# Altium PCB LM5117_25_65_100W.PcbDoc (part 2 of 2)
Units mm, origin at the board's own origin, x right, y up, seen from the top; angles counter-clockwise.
Board outline 73.02 x 159.13 mm, 4 copper layers (Top Layer, GND, Power, Bottom Layer), stack 0.742 mm thick; 149 components, 80 nets, 535 pads, 514 vias.
Unrouted connection lines stored in the file: 2.
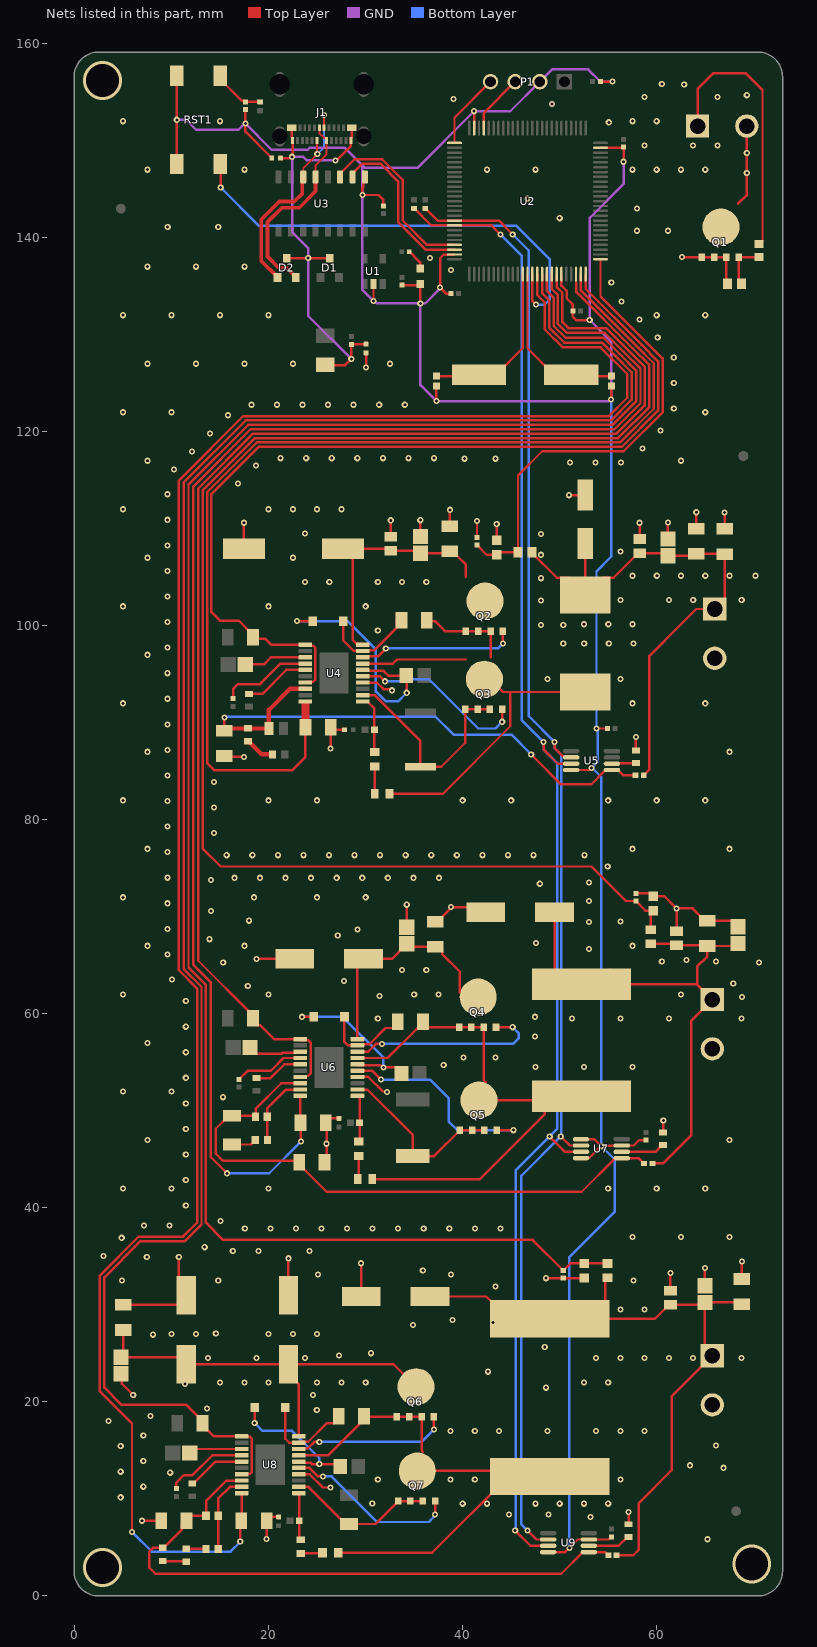
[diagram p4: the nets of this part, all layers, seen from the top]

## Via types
v1: diameter 0.635, hole 0.305, Top Layer to Bottom Layer, 475 vias
v2: diameter 0.5, hole 0.2, Top Layer to Bottom Layer, 36 vias
v3: diameter 4, hole 3.4, Top Layer to Bottom Layer, 3 vias

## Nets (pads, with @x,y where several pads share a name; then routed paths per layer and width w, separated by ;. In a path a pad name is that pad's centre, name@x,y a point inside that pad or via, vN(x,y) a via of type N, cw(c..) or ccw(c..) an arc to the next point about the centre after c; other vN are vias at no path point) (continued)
buck1_EN: C22.1 U2.25 U4.1 U4.7 | length 95.7
  Top Layer w0.254: U4.7@23.847,94.148 23.945,94.246 24.653,94.246 24.874,94.467 24.874,97.729 24.653,97.95 23.945,97.95 U4.1@23.847,98.048 20.316,98.048 19.685,98.679 18.572,98.679 C22.1@18.445,98.806 18.445,99.057 16.968,100.534 15.036,100.534 14.157,101.413 14.157,113.577 19.017,118.437 56.454,118.437 60.201,122.184 60.201,127.251 58.477,128.975 52.736,134.716 U2.25@52.736,136.239
buck1_FB: C14.1 C32.2 R7.1 R13.1 U4.8 U5.5 | length 58.7
  Top Layer w0.254: v1(15.494,90.551) C32.2@15.494,89.184 C32.2@15.718,89.408 ; v1(47.117,86.741) 50.203,83.655 53.302,83.655 54.778,85.131 56.065,85.131 56.614,84.582 R13.1@57.868,84.582
  Top Layer w0.45: C32.2@15.718,89.408 C14.1@20.078,89.408 20.078,91.325 22.251,93.498 U4.8@23.847,93.498
  Bottom Layer w0.254: v1(15.494,90.551) 15.548,90.605 37.284,90.605 39.116,88.773 45.085,88.773 v1(47.117,86.741)
buck1_Iout: C19.2 U2.24 U4.10 | length 111
  Top Layer w0.254: C19.2@23.846,89.535 23.846,86.457 22.479,85.09 14.478,85.09 13.703,85.865 13.703,113.765 18.829,118.891 56.266,118.891 59.747,122.372 59.747,127.063 58.023,128.787 52.236,134.574 U2.24@52.236,136.239
  Top Layer w0.8: C19.2@23.847,89.536 23.847,91.948
buck1_RAMP: C29.1 R12.1 U4.11 | length 6
  Top Layer w0.254: U4.11@29.747,92.198 30.222,92.198 30.959,91.461 C29.1@30.959,89.281 30.959,87.012 R12.1@30.988,86.983
buck1_VCC: C24.1 D4.1 U4.16 | length 25.8
  Top Layer w0.254: v1@22.987,100.457 D4.1@24.587,100.457 ; U4.16@29.747,95.448 29.845,95.35 31.904,95.35 32.385,94.869 C24.1@34.253,94.869 34.29,94.832 v1(34.29,93.091)
  Bottom Layer w0.254: v1(22.96,100.475) 28.176,100.475 31.115,97.536 31.115,93.218 32.131,92.202 33.401,92.202 v1(34.29,93.091)
buck1_Vout: C31.2 R15.1 R16.2 U2.26 | length 48.7
  Top Layer w0.254: C31.2@41.529,108.312 42.526,107.315 R16.2@43.561,107.315 43.815,107.569 R15.1@45.757,107.569 45.757,115.48 48.26,117.983 56.642,117.983 60.655,121.996 60.655,127.559 54.261,133.953 U2.26@54.261,137.764
buck2_COMP: C36.2 C37.2 U6.9 | length 7.5
  Top Layer w0.254: C37.2@19.931,46.99 19.917,47.003 19.917,49.39 C36.2@19.904,49.403 19.904,50.257 21.844,52.197 23.307,52.197 U6.9@23.309,52.194
buck2_EN: C42.1 U2.19 U6.1 U6.7 | length 137.6
  Top Layer w0.254: U6.7@23.309,53.494 23.407,53.592 24.116,53.592 24.384,53.86 24.384,57.028 24.116,57.296 23.407,57.296 U6.1@23.309,57.394 20.614,57.394 19.171,58.837 18.92,58.837 18.445,59.312 C42.1@18.445,59.563 18.445,59.814 12.795,65.465 12.795,114.141 18.453,119.799 55.89,119.799 58.839,122.748 58.839,126.687 57.115,128.411 54.843,130.683 50.948,130.683 50.33,131.301 50.33,134.328 49.736,134.922 U2.19@49.736,136.239
buck2_FB: C36.1 C51.2 R17.1 R22.1 U6.8 U7.5 | length 61.2
  Top Layer w0.254: U6.8@23.309,52.844 21.348,52.844 18.738,50.234 18.738,49.595 18.625,49.482 R17.1@16.256,49.482 15.931,49.482 14.605,48.156 14.605,45.593 15.367,44.831 23.084,44.831 C51.2@23.211,44.704 23.211,44.453 23.685,43.978 23.713,43.978 26.035,41.656 52.324,41.656 55.794,45.126 U7.5@56.456,45.126 58.183,45.126 58.732,44.577 R22.1@58.757,44.577
buck2_Iout: C39.2 U2.18 U6.10 | length 154.9
  Top Layer w0.254: v1(15.748,43.561) 14.097,45.212 14.097,63.246 12.295,65.048 12.295,114.348 18.2,120.253 55.702,120.253 58.385,122.936 58.385,126.499 56.661,128.223 54.701,130.183 50.806,130.183 49.876,131.113 49.876,134.075 49.236,134.715 U2.18@49.236,136.239 ; U6.10@23.309,51.544 23.309,48.796 C39.2@23.338,48.768 23.368,48.738 v1@23.368,46.863
  Bottom Layer w0.254: v1(15.748,43.561) 20.114,43.561 v1(23.389,46.837)
buck2_RAMP: C48.1 R21.1 U6.11 | length 4.9
  Top Layer w0.254: U6.11@29.209,51.544 29.337,51.544 29.435,51.446 C48.1@29.435,48.768 29.435,46.949 R21.1@29.337,46.851
buck2_VCC: C44.1 D5.1 U6.16 | length 17.1
  Top Layer w0.254: v1@23.368,59.69 v1(23.495,59.69) D5.1@24.714,59.69 ; U6.16@29.209,54.794 29.307,54.696 31.561,54.696 31.782,54.475 33.169,54.475 33.745,53.899 C44.1@33.745,53.848
  Bottom Layer w0.254: v1(23.495,59.69) 27.686,59.69 31.877,55.499 v1@31.877,54.8
  other v1: 31.877,54.483
buck2_Vout: C50.2 R24.1 R25.2 U2.23 | length 154.5
  Top Layer w0.254: U2.23@51.736,136.239 51.736,135.337 51.782,135.291 51.782,134.386 57.569,128.599 59.293,126.875 59.293,122.56 56.078,119.345 18.641,119.345 13.249,113.953 13.249,77.048 15.113,75.184 53.34,75.184 56.896,71.628 57.893,71.628 C50.2@57.912,71.609 58.897,70.624 R25.2@59.69,70.624 59.436,70.37 R24.1@59.436,68.67
buck3_COMP: C55.2 C57.2 U8.9 | length 8.1
  Top Layer w0.254: C57.2@14.851,4.826 14.851,8.253 C55.2@14.849,8.255 14.849,10.023 16.069,11.243 U8.9@17.272,11.243
buck3_EN: C62.1 U2.16 U8.1 U8.7 | length 191.9
  Top Layer w0.254: U8.7@17.272,12.543 17.321,12.592 18.15,12.592 18.299,12.74 18.299,16.226 18.141,16.385 17.33,16.385 U8.1@17.272,16.443 14.415,16.443 13.804,17.054 13.713,17.054 13.238,17.529 C62.1@13.238,17.78 13.238,18.031 11.585,19.685 4.899,19.685 3.121,21.463 3.121,32.839 6.858,36.576 11.43,36.576 13.135,38.281 13.135,62.788 11.341,64.582 11.341,64.597 11.295,64.643 11.295,114.762 17.694,121.161 55.326,121.161 57.477,123.312 57.477,126.123 55.753,127.847 54.417,129.183 50.522,129.183 48.968,130.737 48.968,133.569 48.236,134.301 U2.16@48.236,136.239
buck3_FB: C55.1 C71.2 R26.1 R32.1 U8.8 U9.5 | length 64
  Top Layer w0.254: U8.8@17.272,11.893 15.703,11.893 13.599,9.789 C55.1@13.599,8.255 12.062,8.255 11.587,7.78 C71.2@11.587,7.747 11.113,7.272 11.113,6.845 9.221,4.953 R26.1@9.144,4.953 8.128,4.953 7.747,4.572 7.747,2.921 8.382,2.286 50.212,2.286 52.442,4.516 U9.5@53.067,4.516 54.724,4.516 55.049,4.191 R32.1@55.074,4.191
buck3_iout: C59.2 U2.15 U8.10 | length 203.5
  Top Layer w0.254: v1(5.969,6.604) 5.969,17.78 2.667,21.082 2.667,33.027 6.67,37.03 11.242,37.03 12.681,38.469 12.681,62.6 10.795,64.486 10.795,64.643 10.795,114.969 17.441,121.615 55.138,121.615 57.023,123.5 57.023,125.935 54.275,128.683 50.38,128.683 48.514,130.549 48.514,133.316 47.736,134.094 U2.15@47.736,136.239 ; v1(17.127,5.604) 17.127,7.633 C59.2@17.242,7.747 17.272,7.777 U8.10@17.272,10.593
  Bottom Layer w0.254: v1(5.969,6.604) 8.001,4.572 16.129,4.572 v1@17.145,5.588
buck3_RAMP: C68.1 R31.1 U8.11 | length 4.9
  Top Layer w0.254: U8.11@23.172,10.593 23.212,10.553 C68.1@23.212,7.747 23.212,5.936 R31.1@23.368,5.78
buck3_VCC: C64.1 D6.1 U8.16 | length 14.9
  Top Layer w0.254: v1(18.618,17.831) D6.1@18.618,19.431 ; U8.16@23.172,13.843 23.27,13.745 24.353,13.745 24.509,13.589 27.178,13.589 C64.1@27.432,13.335
  Bottom Layer w0.254: v1(18.618,17.831) 19.431,17.018 22.479,17.018 25.273,14.224 v1(25.273,13.589)
buck3_Vout: C70.2 R34.1 R35.2 U2.17 | length 189.5
  Top Layer w0.254: U2.17@48.736,136.239 48.736,134.508 49.422,133.822 49.422,130.925 50.664,129.683 54.559,129.683 56.207,128.035 57.931,126.311 57.931,123.124 55.514,120.707 17.947,120.707 11.795,114.555 11.795,64.77 13.589,62.976 13.589,38.481 15.367,36.703 47.263,36.703 C70.2@50.419,33.547 51.15,34.278 R35.2@52.578,34.278 54.966,34.278 R34.1@54.991,34.253
GND_3V3: C3.1 C4.1 C5.1 C6.1 C7.1 C8.1 C9.2 C10.2 C11.1 C30.2 C49.2 C69.2 D3.1 NT1.1 P1.2 RST1.1 RST1.2 U1.2 U2.20 U2.49 U2.74 U2.99 U3.1 U5.4 U7.1 U7.4 U7.7 U9.4 U9.7 | length 320.4
  Top Layer w0.254: RST1.1@10.577,147.596 10.587,147.606 v1(10.587,152.151) RST1.2@10.587,156.696 ; C8.1@17.653,153.197 v1(17.653,151.765) 17.653,150.934 NT1.1@20.378,148.209 ; U3.1@29.972,146.26 29.824,146.112 29.824,145.224 29.718,145.118 v1(29.718,144.399) 31.369,144.399 31.877,143.891 C11.1@31.877,143.275 ; v1(30.861,133.477) U1.2@30.861,135.225 ; C3.1@33.782,135.109 35.579,135.109 D3.1@35.687,135.217 v1@35.687,133.477 ; v1@37.338,123.19 C9.2@37.338,124.71 ; C6.1@38.843,134.239 38.84,134.242 38.351,134.242 v1(37.719,134.874) 37.719,137.883 38.1,138.264 U2.99@39.211,138.264 ; U2.74@41.236,151.289 v1(41.236,153.035) ; U9.4@48.867,4.516 50.617,4.516 v1(51.054,4.953) 51.917,5.816 U9.7@53.067,5.816 55.111,5.816 C69.2@55.372,6.077 ; U2.20@50.236,136.239 50.236,135.064 50.784,134.516 50.784,133.734 51.416,133.102 C4.1@51.416,132.461 51.416,131.826 51.742,131.5 v1(53.149,131.5) ; U5.4@51.24,85.131 53.127,85.131 v1(53.34,85.344) ; U7.4@52.256,45.126 52.294,45.164 53.107,45.164 v1@54.327,46.384 ; U7.1@52.256,47.076 53.635,47.076 v1@54.327,46.384 ; v1(53.848,89.408) C30.2@54.972,89.408 ; C7.1@54.248,156.083 v1@55.499,156.083 ; U2.49@54.261,149.264 54.263,149.266 56.575,149.266 C5.1@56.642,149.333 v1(56.642,147.828) ; v1(54.356,46.355) v1@54.327,46.384 ; v1@55.372,123.317 C10.2@55.372,124.712 ; C49.2@58.928,46.971 58.237,46.971 57.692,46.426 U7.7@56.456,46.426 56.443,46.413 54.356,46.413 v1@54.327,46.384
  GND w0.254: v1(10.587,152.151) 11.552,152.151 12.573,151.13 16.933,151.13 17.568,151.765 v1(17.653,151.765) 20.358,149.06 24.086,149.06 24.283,149.257 27.908,149.257 29.718,147.447 ; v1@37.719,134.747 36.195,133.223 v1(35.687,133.223) ; v1@55.094,123.157 v1(37.341,123.157) 35.687,124.811 v1(35.687,133.223) ; v1(55.347,123.307) 55.347,129.302 v1(53.149,131.5) 53.149,142.049 56.642,145.542 v1(56.642,147.828) ; v1(55.5,156.095) 54.236,156.095 52.978,157.353 49.276,157.353 P1.2@48.006,156.083 44.958,153.035 v1(41.236,153.035) 35.394,147.193 29.972,147.193 29.718,147.447 ; 29.718,147.447 v1(29.718,144.399) 29.718,134.62 v1(30.861,133.477) 30.946,133.477 31.2,133.223 v1(35.687,133.223)
  Bottom Layer w0.254: v1(51.054,4.953) 51.054,34.925 55.753,39.624 55.753,44.958 v1(54.356,46.355) 54.356,84.382 v1@53.326,85.412 ; v1(53.34,85.344) 53.985,85.989 v1@53.985,89.168 ; v1(53.848,89.408) 53.848,105.608 55.347,107.107 v1(55.347,123.307)
GND_5V: C1.1 C2.2 D1.3 D2.3 J1.A1 J1.A12 J1.B1 J1.B12 NT1.2 NT3.1 | length 46.8
  Top Layer w0.254: NT1.2@21.278,148.209 22.249,148.209 22.376,148.336 v1(22.479,148.336) ; D2.3@21.91,137.89 v1(24.13,137.89) D1.3@26.35,137.89 ; J1.B1@22.427,151.327 22.427,150.327 22.527,150.227 J1.A12@22.527,150.027 v1@22.527,148.336 ; C2.2@25.908,126.897 25.932,126.873 27.94,126.873 v1(28.575,127.508) C1.1@28.575,129.013 28.594,129.032 NT3.1@30.099,129.032 ; v1@27.001,147.905 28.527,149.431 J1.A1@28.527,150.027 28.527,150.227 28.627,150.327 J1.B12@28.627,151.327
  GND w0.254: v1(26.937,147.968) 23.99,147.968 23.622,148.336 v1(22.479,148.336) 22.479,140.589 24.13,138.938 v1(24.13,137.89) 24.13,131.953 v1(28.575,127.508)
I2C1_SCL: R5.2 U2.92 U5.2 U7.2 U9.2 | length 155.5
  Top Layer w0.254: R5.2@36.195,143.002 36.22,143.002 37.458,141.764 U2.92@39.211,141.764 43.783,141.764 v1(45.212,140.335) ; v1(46.736,6.731) 47.651,5.816 U9.2@48.867,5.816 ; v1(49.53,88.011) 49.53,87.385 50.386,86.529 50.464,86.529 50.562,86.431 U5.2@51.24,86.431 ; v1(50.165,47.371) 51.11,46.426 U7.2@52.256,46.426
  Bottom Layer w0.254: v1(45.212,140.335) 46.863,138.684 46.863,90.678 v1(49.53,88.011) 49.53,87.376 50.238,86.668 50.238,47.945 50.238,47.444 46.101,43.307 46.101,7.366 v1(46.736,6.731)
I2C1_SDA: R6.2 U2.93 U5.3 U7.3 U9.3 | length 159.9
  Top Layer w0.254: R6.2@35.052,143.002 35.077,143.002 36.815,141.264 U2.93@39.211,141.264 43.013,141.264 v1@43.878,140.398 ; v1@45.439,6.758 47.031,5.166 U9.3@48.867,5.166 ; v1(48.387,88.011) 48.387,87.249 49.855,85.781 U5.3@51.24,85.781 ; v1@49.014,47.379 v1(49.022,47.371) 50.617,45.776 U7.3@52.256,45.776
  Bottom Layer w0.254: v1(43.942,140.335) 46.164,138.113 46.164,90.234 v1(48.387,88.011) 48.387,87.249 49.784,85.852 49.784,48.133 v1(49.022,47.371) 45.539,43.888 45.539,6.804 v1(45.466,6.731)
NetC8_2: C8.2 R4.1 RST1.4 | length 5.4
  Top Layer w0.254: RST1.4@15.067,156.696 15.067,156.336 17.273,154.13 17.52,154.13 C8.2@17.653,153.997 17.655,153.995 19.175,153.995 R4.1@19.177,153.993
NetC9_1: C9.1 U2.12 Y1.2 | length 16
  Top Layer w0.254: C9.1@37.338,125.73 41.605,125.73 Y1.2@41.732,125.857 ; Y1.2@43.49,125.857 46.236,128.603 U2.12@46.236,136.239
NetC10_1: C10.1 U2.13 Y1.1 | length 17.5
  Top Layer w0.254: U2.13@46.736,136.239 46.736,128.603 49.482,125.857 Y1.1@51.232,125.857 51.357,125.732 C10.1@55.372,125.732
NetC17_1: C17.1 R7.2 | length 3.1
  Top Layer w0.254: R7.2@17.907,88.096 R7.2@17.984,88.096
  Top Layer w0.45: R7.2@17.984,88.096 19.339,86.741 C17.1@20.455,86.741
NetC18_1: C18.1 U4.4 | length 9.5
  Top Layer w0.254: C18.1@16.383,92.494 16.383,93.472 16.891,93.98 19.177,93.98 21.295,96.098 U4.4@23.847,96.098
NetC21_1: C21.1 U4.3 | length 6.5
  Top Layer w0.254: C21.1@17.628,96.012 19.558,96.012 20.294,96.748 U4.3@23.847,96.748
NetC28_1: C28.1 L1.1 Q2.1 Q2.2 Q2.3 Q3.5-6-7-8 R11.2 U4.17 | length 50.4
  Top Layer w0.254: U4.17@29.747,96.098 32.852,96.098 33.274,96.52 40.386,96.52 ; R11.2@32.5,82.677 37.997,82.677 44.958,89.638 44.958,93.171 ; C28.1@36.352,100.584 36.455,100.482 37.186,100.482 38.227,99.441 Q2.1@40.386,99.441 Q2.2@41.656,99.441 Q2.3@42.926,99.441 42.926,96.774 ; Q3.5-6-7-8@42.291,94.488 42.897,94.488 44.214,93.171 44.958,93.171 ; L1.1@52.705,93.171 44.958,93.171
  other v1: 57.556,92.008 48.806,94.508 56.306,94.508
NetC28_2: C28.2 D4.2 U4.19 | length 10.8
  Top Layer w0.254: D4.2@27.737,100.457 27.737,98.501 28.829,97.409 29.736,97.409 U4.19@29.747,97.398 29.845,97.496 30.948,97.496 33.277,99.825 33.277,100.752 C28.2@33.377,100.851 ; C28.2@33.276,101.06 33.43,100.905 C28.2@33.752,100.584 ; C28.2@33.881,100.482 C28.2@33.983,100.584
NetC37_1: C37.1 R17.2 | length 2.6
  Top Layer w0.254: R17.2@16.256,46.53 18.244,46.53 18.677,46.963 C37.1@18.677,46.99
NetC38_1: C38.1 U6.4 | length 7.2
  Top Layer w0.254: C38.1@17.018,53.251 17.888,54.121 20.267,54.121 21.59,55.444 U6.4@23.309,55.444
NetC41_1: C41.1 U6.3 | length 5.5
  Top Layer w0.254: C41.1@18.136,56.515 18.771,55.88 21.384,55.88 21.5,55.996 23.211,55.996 U6.3@23.309,56.094
NetC47_1: C47.1 L2.1 Q4.1 Q4.2 Q4.3 Q5.5-6-7-8 R20.2 U6.17 | length 54.8
  Top Layer w0.254: U6.17@29.209,55.444 32.321,55.444 35.333,58.456 35.497,58.456 35.971,58.931 C47.1@35.971,59.182 ; R20.2@30.737,42.968 41.825,42.968 48.527,49.67 48.527,50.029 50.025,51.527 L2.1@50.384,51.527 ; C47.1@35.971,59.094 36.053,59.012 36.446,58.62 Q4.1@39.681,58.62 Q4.2@40.951,58.62 Q4.3@42.221,58.62 42.221,53.156 42.418,52.959 ; Q5.5-6-7-8@41.726,51.108 48.43,51.108 48.849,51.527 L2.1@50.384,51.527 ; L2.1@52.324,51.527 L2.1@50.384,51.527
  other v1: 47.556,54.508 52.556,54.508 57.556,54.508 38.1,54.737 40.132,55.499 43.434,55.499
NetC47_2: C47.2 D5.2 U6.19 | length 9.3
  Top Layer w0.254: D5.2@27.864,59.69 27.864,57.099 28.194,56.769 29.234,56.769 29.307,56.842 30.419,56.842 32.115,58.538 32.896,58.538 33.371,59.013 C47.2@33.371,59.182
NetC57_1: C57.1 R27.2 | length 2.1
  Top Layer w0.254: R27.2@11.557,4.868 13.556,4.868 C57.1@13.597,4.826
NetC58_1: C58.1 U8.4 | length 8.5
  Top Layer w0.254: C58.1@10.541,11.068 10.541,11.684 11.303,12.446 12.192,12.446 14.239,14.493 U8.4@17.272,14.493
NetC61_1: C61.1 U8.3 | length 4.5
  Top Layer w0.254: 12.768,15.143 U8.3@17.272,15.143
NetC67_1: C67.1 L3.1 Q6.1 Q6.2 Q6.3 Q7.5-6-7-8 R30.2 U8.17 | length 57.1
  Top Layer w0.254: U8.17@23.172,14.493 26.177,14.493 29.401,17.717 29.401,18.067 C67.1@29.875,18.542 ; R30.2@27.216,4.445 36.895,4.445 44.775,12.324 L3.1@49.022,12.324 48.465,12.881 Q7.5-6-7-8@35.376,12.881 ; C67.1@29.875,18.457 Q6.1@33.274,18.457 Q6.2@34.544,18.457 Q6.3@35.814,18.457 35.814,14.986 35.941,14.859
  other v1: 53.213,8.128 44.831,8.382 48.895,8.382 40.056,9.508 42.556,9.508 47.556,9.508 50.056,9.508 52.556,9.508 55.056,9.508 31.306,12.008 38.806,12.008 41.306,12.008 56.306,12.008 38.806,17.008 41.306,17.008 43.806,17.008 48.806,17.008 53.806,17.008 56.306,17.008 58.806,17.008
NetC67_2: C67.2 D6.2 U8.19 | length 10.2
  Top Layer w0.254: D6.2@21.768,19.431 21.768,16.205 22.18,15.793 U8.19@23.172,15.793 23.27,15.891 24.139,15.891 26.064,17.816 26.8,17.816 27.275,18.291 C67.2@27.275,18.542
NetD3_2: D3.2 R3.1 | length 2.2
  Top Layer w0.254: R3.1@34.563,138.557 35.671,137.449 35.671,136.833 D3.2@35.687,136.817
NetJ2_2: J2.2 Q1.5-6-7-8 | length 9.4
  Top Layer w0.254: Q1.5-6-7-8@66.675,141.097 Q1.5-6-7-8@67.056,141.478 ; 68.453,143.51 69.342,144.399 J2.2@69.342,151.511 J2.2@68.961,151.13
  other v1: 58.039,140.716 61.214,140.716 58.039,143.002 69.342,146.685 69.342,148.717 69.342,154.686
NetQ1_4: Q1.4 R1.1 R2.2 | length 5
  Top Layer w0.254: R2.2@68.797,135.255 68.51,135.542 Q1.4@68.51,137.995 70.598,137.995 R1.1@70.612,138.009
NetQ2_4: Q2.4 U4.18 | length 16.3
  Top Layer w0.254: U4.18@29.747,96.748 29.845,96.846 31.314,96.846 v1(32.131,97.663) ; v1(44.196,98.171) Q2.4@44.196,99.441
  Bottom Layer w0.254: v1(32.131,97.663) 43.688,97.663 v1(44.196,98.171)
NetQ3_1: Q3.1 Q3.2 Q3.3 R36.2 U4.12 | length 22.2
  Top Layer w0.254: U4.12@29.747,92.848 30.977,92.848 35.687,88.138 R36.2@35.687,85.471 37.846,85.471 40.316,87.941 Q3.1@40.316,91.386 Q3.2@41.586,91.386 Q3.3@42.856,91.386
NetQ3_4: Q3.4 U4.15 | length 18.4
  Top Layer w0.254: U4.15@29.747,94.798 31.518,94.798 v1(32.042,94.274) ; v1(44.126,90.1) Q3.4@44.126,91.386
  Bottom Layer w0.254: v1(32.042,94.274) 34.253,94.274 34.468,94.488 36.576,94.488 41.656,89.408 43.434,89.408 v1(44.126,90.1)
NetQ4_4: Q4.4 U6.18 | length 20.3
  Top Layer w0.254: U6.18@29.209,56.094 30.313,56.094 31.115,56.896 v1(31.75,56.896) ; Q4.4@43.491,58.62 v1(45.212,58.62)
  Bottom Layer w0.254: v1(31.75,56.896) 45.228,56.896 45.847,57.515 45.847,57.985 v1(45.212,58.62)
NetQ5_1: Q5.1 Q5.2 Q5.3 R19.2 U6.12 | length 18.3
  Top Layer w0.254: U6.12@29.209,52.194 30.222,52.194 34.925,47.491 R19.2@34.925,45.329 37.111,45.329 39.751,47.968 Q5.1@39.751,48.006 Q5.2@41.021,48.006 Q5.3@42.291,48.006
NetQ5_4: Q5.4 U6.15 | length 21.7
  Top Layer w0.254: U6.15@29.209,54.144 30.692,54.144 v1(31.623,53.213) ; Q5.4@43.561,48.006 v1(45.282,48.006)
  Bottom Layer w0.254: v1(31.623,53.213) 36.703,53.213 38.608,51.308 38.608,48.895 39.497,48.006 v1(45.282,48.006)
NetQ6_4: Q6.4 U8.18 | length 16.1
  Top Layer w0.254: U8.18@23.172,15.143 23.27,15.241 24.131,15.241 24.765,15.875 v1(25.273,15.875) ; v1(37.084,17.145) Q6.4@37.084,18.457
  Bottom Layer w0.254: v1(25.273,15.875) 35.814,15.875 v1(37.084,17.145)
NetQ7_1: Q7.1 Q7.2 Q7.3 R29.2 U8.12 | length 15.4
  Top Layer w0.254: U8.12@23.172,11.243 24.167,11.243 27.996,7.414 R29.2@28.321,7.414 31.074,7.414 33.401,9.741 Q7.1@33.401,9.779 Q7.2@34.671,9.779 Q7.3@35.941,9.779
NetQ7_4: Q7.4 U8.15 | length 18.1
  Top Layer w0.254: U8.15@23.172,13.193 24.263,13.193 25.137,12.319 v1(25.654,12.319) ; v1(37.211,8.382) Q7.4@37.211,9.779
  Bottom Layer w0.254: v1(25.654,12.319) 26.543,12.319 31.242,7.62 36.576,7.62 36.779,7.823 36.779,7.847 37.211,8.279 v1(37.211,8.382)
NetR8_2: R8.2 U4.5 | length 6.8
  Top Layer w0.254: R8.2@18.034,92.979 19.404,92.979 21.873,95.448 U4.5@23.847,95.448
NetR11_1: R11.1 R12.2 | length 2.8
  Top Layer w0.254: R12.2@30.988,85.483 30.988,82.689 R11.1@31,82.677
NetR14_1: R14.1 U5.6 | length 2.5
  Top Layer w0.254: U5.6@55.44,85.781 55.468,85.809 57.884,85.809 R14.1@57.912,85.837
NetR18_2: R18.2 U6.5 | length 5.1
  Top Layer w0.254: R18.2@18.796,53.374 20.242,53.374 21.662,54.794 U6.5@23.309,54.794
NetR20_1: R20.1 R21.2 | length 2.4
  Top Layer w0.254: R20.1@29.237,42.968 29.337,43.068 R21.2@29.337,45.351
NetR23_1: R23.1 U7.6 | length 4.5
  Top Layer w0.254: U7.6@56.456,45.776 59.915,45.776 60.606,46.467 R23.1@60.706,46.467
NetR26_2: R26.2 R27.1 | length 2.4
  Top Layer w0.254: R26.2@9.144,3.6 9.187,3.557 11.514,3.557 R27.1@11.557,3.514
NetR28_2: R28.2 U8.5 | length 6
  Top Layer w0.254: R28.2@12.192,11.572 12.292,11.572 14.563,13.843 U8.5@17.272,13.843
NetR30_1: R30.1 R31.2 | length 2.3
  Top Layer w0.254: R31.2@23.368,4.38 25.551,4.38 R30.1@25.616,4.445
NetR33_1: R33.1 U9.6 | length 4.5
  Top Layer w0.254: U9.6@53.067,5.166 56.135,5.166 57.05,6.081 R33.1@57.15,6.081
NetRST1_3: RST1.3 U2.14 | length 48.5
  Top Layer w0.254: RST1.3@15.067,147.596 15.113,147.55 v1(15.113,145.161) ; U2.14@47.236,136.239 47.236,133.485 v1(47.625,133.096)
  Bottom Layer w0.254: v1(15.113,145.161) 19.05,141.224 45.593,141.224 49.022,137.795 49.022,133.604 48.514,133.096 v1(47.625,133.096)
PGND: C12.2 C13.2 C15.2 C16.1 C19.1 C20.1 C23.2 C25.2 C26.1 C27.1 C31.1 C32.1 C33.1 C34.2 C35.1 C39.1 C40.1 C43.2 C45.2 C46.1 C50.1 C51.1 C52.1 C53.1 C54.2 C56.1 C59.1 C60.1 C63.2 C65.2 C66.1 C70.1 C71.1 J3.2 J4.2 J5.2 NT2.2 NT3.2 NT4.2 NT5.2 Q1.1 Q1.2 Q1.3 R2.1 R14.2 R16.1 R23.2 R25.1 R33.2 R35.1 U4.14 U6.14 U8.14 | length 116.4
  Top Layer w0.254: C54.2@4.826,22.885 4.933,22.778 4.933,21.864 v1@6.253,20.544 ; C56.1@5.08,30.002 10.684,30.002 11.557,30.875 C53.1@11.557,30.982 10.795,31.744 v1(10.795,34.925) ; v1(6.985,7.747) C71.1@8.987,7.747 ; C32.1@15.494,86.584 15.591,86.487 v1(17.526,86.487) ; C12.2@17.506,107.95 v1@17.506,110.591 ; v1@18.796,65.659 C33.1@22.739,65.659 ; v1(19.842,5.872) C59.1@19.842,7.747 20.234,8.139 NT2.2@21.082,8.139 ; C52.1@22.098,32.512 v1(22.098,34.798) ; U8.14@23.172,12.543 24.27,12.543 25.637,11.176 v1(26.416,11.176) ; C51.1@25.811,44.955 C51.1@25.811,44.704 26.035,44.928 v1(26.035,46.609) 26.035,48.671 C39.1@25.938,48.768 26.388,49.218 NT4.2@27.305,49.218 ; v1(26.446,87.35) 26.446,89.281 NT5.2@27.871,89.281 ; C60.1@28.597,30.861 C60.1@29.597,30.861 29.597,34.284 v1(29.591,34.29) ; U6.14@29.209,53.494 30.326,53.494 31.828,51.992 32.209,51.992 v1(32.258,51.943) ; U4.14@29.747,94.148 31.201,94.148 31.877,93.472 v1@32.512,93.472 ; v1(30.099,126.619) NT3.2@30.099,128.132 ; C13.2@32.639,109.184 v1(32.639,110.871) ; C34.2@34.29,68.936 v1(34.29,71.247) ; C15.2@35.687,109.195 v1(35.687,110.882) ; C35.1@37.211,69.499 37.462,69.499 38.956,70.993 41.916,70.993 C40.1@42.424,70.485 ; C16.1@38.735,110.266 v1(38.735,111.953) ; C31.1@41.529,109.112 v1(41.529,110.799) ; R16.1@43.561,108.815 v1(43.561,110.502) ; v1(48.66,32.747) C70.1@50.419,32.747 52.547,32.747 R35.1@52.578,32.778 ; v1(51.018,113.458) C20.1@52.705,113.458 ; R33.2@57.15,7.381 v1(57.15,8.636) ; C50.1@57.912,72.409 59.405,72.409 R25.1@59.69,72.124 60.845,72.124 v1(62.103,70.866) ; R14.2@57.912,87.137 v1(57.912,88.519) ; C23.2@58.293,108.93 v1(58.293,110.617) ; R23.2@60.706,47.767 v1@60.706,49.022 ; C25.2@61.214,108.941 v1(61.214,110.628) ; C63.2@61.468,31.46 v1(61.468,33.274) ; C43.2@62.103,68.508 v1(62.103,70.866) ; v1(62.665,137.995) Q1.1@64.7,137.995 Q1.2@65.97,137.995 Q1.3@67.24,137.995 67.24,135.362 R2.1@67.347,135.255 ; C27.1@64.135,110.012 v1(64.135,111.699) ; C65.2@65.024,31.979 v1(65.024,33.793) ; C26.1@67.056,109.982 v1(67.056,111.669) ; C45.2@68.453,68.967 67.829,69.591 C46.1@65.278,69.591 65.027,69.591 63.751,70.866 v1(62.103,70.866) ; C66.1@68.834,32.669 v1(68.834,34.483)
  other v1: 65.278,5.842 30.734,9.525 4.805,10.166 7.133,11.256 9.906,12.7 4.805,12.801 66.929,13.208 63.5,13.462 7.133,13.891 4.805,15.436 66.167,15.494 7.133,16.526 3.556,18.034 7.874,18.542 13.716,19.304 6.096,20.701 4.953,32.512 14.859,32.512 25.146,33.147 7.493,34.925 3.042,35.048 16.358,35.539 18.993,35.539 24.263,35.539 13.462,35.941 4.905,36.911 57.556,37.008 62.556,37.008 67.556,37.008 17.594,37.867 20.229,37.867 22.864,37.867 25.499,37.867 28.134,37.867 30.769,37.867 33.404,37.867 36.039,37.867 38.674,37.867 41.309,37.867 43.944,37.867 7.207,38.194 9.842,38.194 15.075,38.641 11.517,40.228 5.056,42.008 10.056,42.008 20.056,42.008 55.056,42.008 60.056,42.008 65.056,42.008 11.517,42.863 11.517,45.498 7.556,47.008 67.556,47.008 11.517,48.133 60.735,48.993 11.517,50.768 15.352,51.403 5.056,52.008 10.056,52.008 11.517,53.403 11.517,56.038 7.556,57.008 11.517,58.673 11.517,61.308 5.056,62.008 20.056,62.008 17.907,62.865 10.104,63.531 15.367,65.278 18.805,65.641 9.631,66.124 7.556,67.008 17.556,67.008 13.97,67.691 9.631,68.759 18.034,69.596 14.097,70.612 38.862,70.993 9.631,71.394 5.056,72.008 18.542,72.009 25.056,72.008 30.056,72.008 14.097,73.787 16.529,74.02 19.164,74.02 21.799,74.02 24.434,74.02 27.069,74.02 29.704,74.02 32.339,74.02 34.974,74.02 37.609,74.02 9.631,74.029 55,75.183 15.734,76.348 18.369,76.348 21.004,76.348 23.639,76.348 26.274,76.348 28.909,76.348 31.544,76.348 34.179,76.348 36.814,76.348 39.449,76.348 42.084,76.348 44.719,76.348 47.354,76.348 52.624,76.348 9.631,76.664 7.556,77.008 57.556,77.008 67.556,77.008 14.413,78.628 9.631,79.299 14.413,81.263 9.631,81.934 5.056,82.008 20.056,82.008 25.056,82.008 40.056,82.008 45.056,82.008 55.056,82.008 60.056,82.008 65.056,82.008 14.413,83.898 9.631,84.569 7.556,87.008 67.556,87.008 9.631,87.204 9.631,89.839 5.056,92.008 65.056,92.008 9.631,92.474 32.766,93.345 9.631,95.109 7.556,97.008 9.631,97.744 9.631,100.379 5.056,102.008 20.056,102.008 9.631,103.014 9.631,105.649 7.556,107.008 9.631,108.284 17.526,110.617 9.631,110.919 5.056,112.008 20.056,112.008 9.631,113.554 16.898,114.672 10.286,116.106 18.761,116.535 51.113,116.819 53.748,116.819 56.383,116.819 7.556,117.008 62.556,117.008 40.259,117.221 43.434,117.221 21.29,117.273 23.925,117.273 26.56,117.273 29.195,117.273 31.83,117.273 34.465,117.273 37.1,117.273 12.149,117.969 58.58,118.275 14.012,119.833 60.443,120.138 15.876,121.696 5.056,122.008 10.056,122.008 65.056,122.008 61.819,122.385 18.278,122.779 20.913,122.779 23.548,122.779 26.183,122.779 28.818,122.779 31.453,122.779 34.088,122.779 61.819,125.02 7.556,127.008 12.556,127.008 17.556,127.008 22.556,127.008 32.556,127.008 61.81,127.655 60.155,129.705 58.291,131.569 5.056,132.008 10.056,132.008 15.056,132.008 20.056,132.008 60.056,132.008 65.056,132.008 56.428,133.432 55.372,135.382 38.862,136.652 7.556,137.008 12.556,137.008 17.556,137.008 36.703,137.922 9.652,141.097 14.859,141.097 50.056,142.008 46.736,144.018 7.556,147.008 17.556,147.008 42.556,147.008 47.556,147.008 55.118,151.892 5.056,152.008 15.056,152.008 49.276,153.797 39.116,154.305
  other v3: 2.921,2.921 69.85,3.302 2.921,156.21
SWCLK: P1.4 U2.76 | length 7.9
  Top Layer w0.254: U2.76@39.211,149.764 39.211,152.368 P1.4@42.926,156.083
SWDIO: P1.3 U2.72 | length 6.1
  Top Layer w0.254: U2.72@42.236,151.289 42.236,152.853 P1.3@45.466,156.083
USART1_RX: U2.98 U3.2 | length 17.4
  Top Layer w0.254: U3.2@28.702,146.26 28.702,146.605 29.725,147.628 31.569,147.628 33.401,145.796 33.401,141.605 36.24,138.766 39.209,138.766 U2.98@39.211,138.764
USART1_TX: U2.97 U3.3 | length 18.8
  Top Layer w0.254: U3.3@27.432,146.26 27.432,146.605 28.909,148.082 31.757,148.082 33.876,145.964 33.876,141.773 36.382,139.266 39.209,139.266 U2.97@39.211,139.264
USB_N: D2.1 J1.A7 J1.B7 U3.6 | length 23.6
  Top Layer w0.2: U3.6@23.531,146.169 U3.6@23.622,146.26 23.622,147.164 v1(25.07,148.613) ; v1@25.027,148.717 J1.A7@25.027,150.027 ; J1.B7@25.777,151.327 v1(25.777,152.629)
  Top Layer w0.381: D2.1@20.96,135.89 20.96,135.94 19.304,137.596 19.304,141.868 21.16,143.724 22.693,143.724 23.531,144.562 U3.6@23.531,146.169
  Bottom Layer w0.2: v1(25.07,148.613) 25.777,149.319 v1(25.777,152.629)
USB_P: D2.2 J1.A6 J1.B6 U3.5 | length 21.1
  Top Layer w0.2: U3.5@24.892,146.26 24.892,147.447 26.027,148.582 J1.A6@26.027,150.027 26.027,150.227 25.977,150.277 25.777,150.277 25.277,150.777 J1.B6@25.277,151.327
  Top Layer w0.381: D2.2@22.86,135.89 22.86,135.94 21.894,136.906 21.082,136.906 19.939,138.049 19.939,141.605 21.423,143.089 23.201,143.089 24.892,144.78 U3.5@24.892,146.26
VIN: C12.1 C13.1 C15.1 C16.2 C33.2 C34.1 C35.2 C52.2 C53.2 C54.1 C56.2 J2.1 Q2.5-6-7-8 Q4.5-6-7-8 Q6.5-6-7-8 R1.2 U4.20 U6.20 U8.20 | length 118.9
  Top Layer w0.254: C56.2@5.08,27.402 5.08,24.867 C54.1@4.826,24.613 10.826,24.613 C53.2@11.557,23.882 C52.2@22.098,23.882 ; U8.20@23.172,16.443 23.172,21.808 22.098,22.882 C52.2@22.098,23.882 ; U6.20@29.209,57.394 29.209,65.029 C33.2@29.839,65.659 32.752,65.659 34.29,67.197 C34.1@34.29,67.208 34.599,66.899 C35.2@37.211,66.899 37.462,66.899 37.937,66.424 37.937,66.173 39.751,64.359 39.751,62.23 ; U4.20@29.747,98.048 29.649,98.146 29.108,98.146 28.702,98.552 28.702,107.027 27.779,107.95 C12.1@27.706,107.95 32.421,107.95 C13.1@32.639,107.732 35.422,107.732 C15.1@35.687,107.467 38.536,107.467 C16.2@38.735,107.666 39.21,107.191 39.494,107.191 40.386,106.299 40.386,105.029 ; Q6.5-6-7-8@35.249,21.559 32.926,23.882 C52.2@22.098,23.882 ; J2.1@64.262,151.511 64.262,155.321 65.913,156.972 69.215,156.972 70.96,155.227 70.96,139.632 70.687,139.359 R1.2@70.612,139.359
  other v1: 25.019,19.177 24.638,20.701 11.43,21.844 15.056,22.008 17.556,22.008 20.056,22.008 25.056,22.008 27.556,22.008 30.056,22.008 13.806,24.508 18.806,24.508 23.806,24.508 27.305,24.765 30.607,25.019 8.128,26.924 10.056,27.008 12.556,27.008 20.056,27.008 22.556,27.008 25.056,27.008 14.605,27.051 31.306,59.508 31.496,61.849 35.056,62.008 37.556,62.008 27.813,63.373 33.806,64.508 36.306,64.508 27.178,68.072 29.21,68.707 31.306,99.508 30.056,102.008 23.806,104.508 26.306,104.508 31.306,104.508 33.806,104.508 36.306,104.508 22.556,107.008 23.806,109.508 22.556,112.008 25.056,112.008 27.556,112.008 57.556,147.008 60.056,147.008 62.556,147.008 65.056,147.008 58.806,149.508 63.806,149.508 66.306,149.508 57.556,152.008 60.056,152.008 58.806,154.508 66.306,154.508 62.886,155.807 60.579,155.829
Vout_25W: C20.2 C23.1 C25.1 C26.2 C27.2 J3.1 L1.2 R13.2 R15.2 | length 56.4
  Top Layer w0.254: R15.2@47.207,107.569 47.207,107.494 49.757,104.944 50.932,104.944 L1.2@52.705,103.171 ; C20.2@52.705,108.458 L1.2@52.705,103.171 ; R13.2@58.718,84.582 58.743,84.582 58.891,84.73 58.891,84.755 59.309,85.173 59.309,96.901 62.564,100.156 64.135,101.727 J3.1@66.04,101.727 67.056,102.743 C26.2@67.056,107.381 67.026,107.412 C27.2@64.135,107.412 63.936,107.213 C25.1@61.214,107.213 60.949,107.478 C23.1@58.293,107.478 58.142,107.478 55.608,104.944 54.478,104.944 L1.2@52.705,103.171
  other v1: 50.419,98.171 52.578,98.171 55.118,98.171 57.658,98.171 48.133,100.076 50.419,100.076 52.564,100.156 55.064,100.156 57.564,100.156 48.133,102.616 56.314,102.656 61.314,102.656 63.814,102.656 68.814,102.656 48.133,104.902 57.564,105.156 60.064,105.156 62.564,105.156 65.064,105.156 67.564,105.156 70.231,105.156 48.133,107.315 56.314,107.656 48.133,109.474
Vout_65W: C40.2 C43.1 C45.1 C46.2 J4.1 L2.2 R22.2 R24.2 | length 59.3
  Top Layer w0.254: C40.2@49.524,70.485 49.524,64.525 51.022,63.027 L2.2@53.747,63.027 ; L2.2@55.245,64.525 L2.2@53.747,63.027 ; R24.2@59.436,67.22 62.193,67.22 62.357,67.056 65.212,67.056 C46.2@65.278,66.99 ; R22.2@59.607,44.552 59.632,44.577 60.706,44.577 63.627,47.498 63.627,59.309 J4.1@65.786,61.468 64.227,63.027 ; C45.1@68.453,67.238 68.204,66.99 C46.2@65.278,66.99 ; L2.2@53.747,63.027 64.227,63.027 ; 64.227,63.027 64.227,64.862 65.278,65.913 C46.2@65.278,66.99
  other v1: 47.498,57.658 51.306,59.508 56.306,59.508 61.306,59.508 68.806,59.508 47.498,59.69 68.834,61.722 62.556,62.008 67.945,63.119 70.612,65.278 60.579,65.405 66.167,65.405 63.119,65.532 53.086,66.675 57.556,67.008 47.625,67.31 53.086,69.469 56.306,69.508 53.086,71.628 48.006,73.406 53.086,73.533
Vout_100W: C60.2 C63.1 C65.1 C66.2 J5.1 L3.2 R32.2 R34.2 | length 70.5
  Top Layer w0.254: C60.2@36.697,30.861 42.483,30.861 44.775,28.57 L3.2@49.022,28.57 L3.2@52.807,28.57 ; R34.2@54.991,32.803 54.737,32.549 54.737,30.355 52.951,28.57 L3.2@52.807,28.57 ; R32.2@55.924,4.191 57.634,4.191 58.217,4.775 58.217,9.576 61.595,12.954 61.595,20.574 J5.1@65.786,24.765 65.024,25.527 C65.1@65.024,30.251 ; C66.2@68.834,30.069 68.652,30.251 C65.1@65.024,30.251 ; L3.2@52.807,28.57 59.879,28.57 61.317,30.008 C63.1@61.468,30.008 64.781,30.008 C65.1@65.024,30.251
  other v1: 48.641,21.463 52.556,22.008 55.056,22.008 42.672,23.114 53.806,24.508 56.306,24.508 58.806,24.508 61.306,24.508 63.806,24.508 68.806,24.508 48.514,25.654 34.925,27.94 43.18,28.194 38.989,28.448 56.306,29.508 58.806,29.508 43.434,31.877 57.658,32.512 38.862,33.147 35.941,33.528
pads on no net: FID1.1 FID2.1 FID3.1 FID4.1 FID5.1 FID6.1 J1.1 J1.2 J1.3 J1.4 J1.A2 J1.A3 J1.A5 J1.A8 J1.A10 J1.A11 J1.B2 J1.B3 J1.B5 J1.B8 J1.B10 J1.B11 U1.4 U2.1 U2.2 U2.3 U2.4 U2.5 U2.7 U2.8 U2.9 U2.10 U2.11 U2.27 U2.29 U2.30 U2.31 U2.32 U2.33 U2.34 U2.35 U2.36 U2.37 U2.38 U2.39 U2.40 U2.41 U2.42 U2.43 U2.44 U2.45 U2.46 U2.47 U2.48 U2.51 U2.52 U2.53 U2.54 U2.55 U2.56 U2.57 U2.58 U2.59 U2.60 U2.61 U2.62 U2.63 U2.64 U2.65 U2.66 U2.67 U2.68 U2.69 U2.70 U2.71 U2.73 U2.77 U2.78 U2.79 U2.80 U2.81 U2.82 U2.83 U2.84 U2.85 U2.86 U2.87 U2.88 U2.89 U2.90 U2.91 U2.94 U2.95 U2.96 U3.7 U3.8 U3.9 U3.10 U3.11 U3.12 U3.13 U3.14 U3.15 U4.2 U4.21 U6.2 U6.21 U8.2 U8.21
copper on no net:
  other v2: 19.222,12.018 20.222,12.018 21.222,12.018 19.222,13.018 20.222,13.018 21.222,13.018 19.222,14.018 20.222,14.018 21.222,14.018 19.222,15.018 20.222,15.018 21.222,15.018 25.259,52.969 26.259,52.969 27.259,52.969 25.259,53.969 26.259,53.969 27.259,53.969 25.259,54.969 26.259,54.969 27.259,54.969 25.259,55.969 26.259,55.969 27.259,55.969 25.797,93.623 26.797,93.623 27.797,93.623 25.797,94.623 26.797,94.623 27.797,94.623 25.797,95.623 26.797,95.623 27.797,95.623 25.797,96.623 26.797,96.623 27.797,96.623

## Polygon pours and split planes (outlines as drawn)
PGND on Top Layer "NONET_L-01_P-001" (solid, remove dead copper, pour order 30): 70.739,159.131 73.025,156.845 73.025,2.159 70.866,0 2.54,0 0,2.54 0,156.591 2.54,159.131
NetC47_1 on Top Layer "NONET_L-01_P-001" (solid, remove dead copper, pour order 8): 28.526,55.894 28.54,55.88 29.972,55.88 33.909,59.817 33.909,59.944 33.918,59.944 34.172,60.198 36.449,60.198 36.773,59.874 36.773,59.309 42.799,59.309 43.053,59.055 43.053,58.039 44.704,58.039 46.355,56.388 59.817,56.388 60.579,55.626 60.579,49.784 59.436,48.641 38.735,48.641 37.973,49.403 37.973,53.086 36.195,54.864 28.575,54.864
NetC67_1 on Top Layer "NONET_L-01_P-001" (solid, remove dead copper, pour order 9): 22.225,14.986 23.622,14.986 27.813,19.177 28.321,19.685 30.861,19.685 31.16,19.386 31.204,19.431 60.579,19.431 61.214,18.796 61.214,13.081 55.626,7.493 40.005,7.493 37.211,10.287 31.496,10.287 29.972,11.811 29.972,13.716 29.464,14.097 29.337,14.097 22.225,14.097
NetC28_1 on Top Layer "NONET_L-01_P-001" (solid, remove dead copper, pour order 12): 28.956,96.52 29.972,96.52 34.798,101.346 35.052,101.6 36.703,101.6 38.354,99.949 45.974,99.949 46.355,99.568 46.355,98.298 47.752,96.901 58.547,96.901 59.182,96.266 59.182,91.059 58.039,89.916 45.339,89.916 44.958,90.297 44.958,91.44 44.323,92.075 37.973,92.075 36.83,93.218 36.83,95.504 36.576,95.758 28.956,95.758
VIN on Top Layer "NONET_L-01_P-001" (solid, remove dead copper, pour order 4): 21.717,103.378 23.241,101.854 27.635,101.854 28.321,101.168 28.321,98.298 28.956,97.663 31.115,97.663 33.277,99.825 33.147,99.955 33.147,101.854 36.449,101.854 38.354,99.949 45.593,99.949 46.355,100.711 46.355,105.664 45.339,106.68 42.037,106.68 40.386,108.331 31.115,108.331 30.226,109.22 30.226,113.284 29.845,113.665 22.225,113.665 21.717,113.157
Vout_25W on Top Layer "NONET_L-01_P-001" (solid, remove dead copper, pour order 11): 47.117,111.125 55.626,111.125 57.023,109.728 57.023,108.585 57.404,108.204 71.501,108.204 72.136,107.569 72.136,99.822 71.247,98.933 64.008,98.933 61.976,96.901 47.752,96.901 46.355,98.298 46.355,110.363
Vout_100W on Top Layer "NONET_L-01_P-001" (solid, remove dead copper, pour order 10): 33.02,35.433 46.736,35.433 47.879,34.29 47.879,32.512 48.133,32.258 52.832,32.258 54.102,33.528 59.309,33.528 60.452,32.385 60.452,31.115 60.706,30.861 63.119,30.861 63.5,31.242 71.247,31.242 72.136,30.353 72.136,22.606 71.374,21.844 64.262,21.844 61.849,19.431 40.386,19.431 39.497,20.32 39.497,25.654 38.735,26.416 33.655,26.416 32.639,27.432 32.639,35.052
Vout_65W on Top Layer "NONET_L-01_P-001" (solid, remove dead copper, pour order 7): 45.593,74.168 46.609,75.184 53.34,75.184 53.34,74.549 58.674,69.215 58.674,68.199 59.182,67.691 67.31,67.691 67.691,68.072 70.231,68.072 72.009,66.294 72.009,59.182 71.12,58.293 61.976,58.293 60.071,56.388 46.355,56.388 45.593,57.15
VIN on Top Layer "NONET_L-01_P-001" (solid, remove dead copper, pour order 6): 3.556,28.702 3.556,23.749 6.731,23.749 9.779,20.701 21.463,20.701 22.352,19.812 22.352,16.637 22.86,16.129 24.638,16.129 26.543,18.034 26.543,19.177 27.051,19.685 30.861,19.685 31.16,19.386 39.198,19.386 39.497,19.685 39.497,25.654 38.735,26.416 26.67,26.416 25.4,27.686 6.985,27.686 5.969,28.702
VIN on Top Layer "NONET_L-01_P-001" (solid, remove dead copper, pour order 5): 26.416,68.961 26.416,62.23 28.448,60.198 28.448,57.277 28.702,57.023 30.861,57.023 32.766,58.928 32.766,60.071 32.893,60.198 36.449,60.198 36.703,59.944 36.703,59.309 39.37,59.309 45.212,59.309 45.593,59.69 45.593,65.278 44.958,65.913 40.259,65.913 40.259,66.04 38.227,68.072 33.02,68.072 30.988,70.104 27.432,70.104
NetJ2_2 on Top Layer "NONET_L-01_P-001" (solid, remove dead copper, pour order 3): 67.183,157.861 67.564,158.242 70.993,158.242 72.136,157.099 72.136,139.7 71.374,138.938 56.769,138.938 56.007,139.7 56.007,144.145 56.769,144.907 66.04,144.907 67.183,146.05
VIN on Top Layer "NONET_L-01_P-001" (solid, remove dead copper, pour order 2): 66.802,158.242 56.642,158.242 56.007,157.607 56.007,145.669 56.769,144.907 66.04,144.907 67.183,146.05 67.183,157.734
PGND on Bottom Layer "NONET_L-01_P-001" (solid, remove dead copper, pour order 39): 70.739,159.131 73.025,156.845 73.025,2.159 70.866,0 2.54,0 0,2.54 0,156.591 2.54,159.131
NetC47_1 on Bottom Layer "NONET_L-01_P-001" (solid, remove dead copper, pour order 19): 28.526,55.894 28.54,55.88 29.972,55.88 33.909,59.817 33.909,59.944 33.918,59.944 34.172,60.198 36.449,60.198 36.773,59.874 36.773,59.309 42.799,59.309 43.053,59.055 43.053,58.039 44.704,58.039 46.355,56.388 59.817,56.388 60.579,55.626 60.579,49.784 59.436,48.641 38.735,48.641 37.973,49.403 37.973,53.086 36.195,54.864 28.575,54.864
NetC67_1 on Bottom Layer "NONET_L-01_P-001" (solid, remove dead copper, pour order 25): 22.225,14.986 25.146,14.986 27.813,17.653 27.813,19.177 28.321,19.685 30.861,19.685 31.16,19.386 31.204,19.431 60.579,19.431 61.214,18.796 61.214,13.081 55.626,7.493 40.005,7.493 37.211,10.287 31.496,10.287 29.972,11.811 29.972,13.716 29.464,14.097 29.337,14.097 22.225,14.097
Vout_100W on Bottom Layer "NONET_L-01_P-001" (solid, remove dead copper, pour order 21): 33.02,35.433 46.736,35.433 47.879,34.29 47.879,32.512 48.133,32.258 52.832,32.258 54.102,33.528 59.309,33.528 60.452,32.385 60.452,31.115 60.706,30.861 63.119,30.861 63.5,31.242 71.247,31.242 72.136,30.353 72.136,22.606 71.374,21.844 64.262,21.844 61.849,19.431 40.386,19.431 39.497,20.32 39.497,25.654 38.735,26.416 33.655,26.416 32.639,27.432 32.639,35.052
NetC67_1 on Bottom Layer "NONET_L-01_P-001" (solid, remove dead copper, pour order 20): 22.225,14.986 25.146,14.986 27.813,17.653 27.813,19.177 28.321,19.685 30.861,19.685 31.16,19.386 31.204,19.431 60.579,19.431 61.214,18.796 61.214,13.081 55.626,7.493 40.005,7.493 37.211,10.287 31.496,10.287 29.972,11.811 29.972,13.716 29.464,14.097 29.337,14.097 22.225,14.097
NetC28_1 on Bottom Layer "NONET_L-01_P-001" (solid, remove dead copper, pour order 23): 28.956,96.52 29.972,96.52 34.798,101.346 35.052,101.6 36.703,101.6 38.354,99.949 45.974,99.949 46.355,99.568 46.355,98.298 47.752,96.901 58.547,96.901 59.182,96.266 59.182,91.059 58.039,89.916 45.339,89.916 44.958,90.297 44.958,91.44 44.323,92.075 37.973,92.075 36.83,93.218 36.83,95.504 36.576,95.758 28.956,95.758
VIN on Bottom Layer "NONET_L-01_P-001" (solid, remove dead copper, pour order 24): 3.556,28.702 3.556,23.749 6.731,23.749 9.779,20.701 21.463,20.701 22.352,19.812 22.352,16.637 22.86,16.129 24.638,16.129 26.543,18.034 26.543,19.177 27.051,19.685 30.861,19.685 31.16,19.386 39.198,19.386 39.497,19.685 39.497,25.654 38.735,26.416 26.67,26.416 25.4,27.686 6.985,27.686 5.969,28.702
Vout_25W on Bottom Layer "NONET_L-01_P-001" (solid, remove dead copper, pour order 22): 47.117,111.125 55.626,111.125 57.023,109.728 57.023,108.585 57.404,108.204 71.501,108.204 72.136,107.569 72.136,99.822 71.247,98.933 64.008,98.933 61.976,96.901 47.752,96.901 46.355,98.298 46.355,110.363
Vout_65W on Bottom Layer "NONET_L-01_P-001" (solid, remove dead copper, pour order 18): 45.593,74.168 46.609,75.184 53.34,75.184 53.34,74.549 58.674,69.215 58.674,68.199 59.182,67.691 67.31,67.691 67.691,68.072 70.231,68.072 72.009,66.294 72.009,59.182 71.12,58.293 61.976,58.293 60.071,56.388 46.355,56.388 45.593,57.15
VIN on Bottom Layer "NONET_L-01_P-001" (solid, remove dead copper, pour order 17): 3.556,28.702 3.556,23.749 6.731,23.749 9.779,20.701 21.463,20.701 22.352,19.812 22.352,16.637 22.86,16.129 24.638,16.129 26.543,18.034 26.543,19.177 27.051,19.685 30.861,19.685 31.16,19.386 39.198,19.386 39.497,19.685 39.497,25.654 38.735,26.416 26.67,26.416 25.4,27.686 6.985,27.686 5.969,28.702
VIN on Bottom Layer "NONET_L-01_P-001" (solid, remove dead copper, pour order 16): 26.416,68.961 26.416,62.23 28.448,60.198 28.448,57.277 28.702,57.023 30.861,57.023 32.766,58.928 32.766,60.071 32.893,60.198 36.449,60.198 36.703,59.944 36.703,59.309 39.37,59.309 45.212,59.309 45.593,59.69 45.593,65.278 44.958,65.913 40.259,65.913 40.259,66.04 38.227,68.072 33.02,68.072 30.988,70.104 27.432,70.104
VIN on Bottom Layer "NONET_L-01_P-001" (solid, remove dead copper, pour order 15): 21.717,103.378 23.241,101.854 27.635,101.854 28.321,101.168 28.321,98.298 28.956,97.663 31.115,97.663 33.277,99.825 33.147,99.955 33.147,101.854 36.449,101.854 38.354,99.949 45.593,99.949 46.355,100.711 46.355,105.664 45.339,106.68 42.037,106.68 40.386,108.331 31.115,108.331 30.226,109.22 30.226,113.284 29.845,113.665 22.225,113.665 21.717,113.157
NetJ2_2 on Bottom Layer "NONET_L-01_P-001" (solid, remove dead copper, pour order 14): 67.183,157.861 67.564,158.242 70.993,158.242 72.136,157.099 72.136,139.7 71.374,138.938 56.769,138.938 56.007,139.7 56.007,144.145 56.769,144.907 66.04,144.907 67.183,146.05
VIN on Bottom Layer "NONET_L-01_P-001" (solid, remove dead copper, pour order 13): 66.802,158.242 56.642,158.242 56.007,157.607 56.007,145.669 56.769,144.907 66.04,144.907 67.183,146.05 67.183,157.734
VIN on Power "NONET_L-01_P-001" (solid, remove dead copper, pour order 38): 70.739,159.131 73.025,156.845 73.025,2.159 70.866,0 2.54,0 0,2.54 0,156.591 2.54,159.131
PGND on GND "NONET_L-01_P-001" (solid, remove dead copper, pour order 37): 70.739,159.131 73.025,156.845 73.025,2.159 70.866,0 2.54,0 0,2.54 0,156.591 2.54,159.131

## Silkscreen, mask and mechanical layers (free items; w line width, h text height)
Top Solder:
  the board outline again, w3.5
Bottom Solder:
  the board outline again, w3.5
